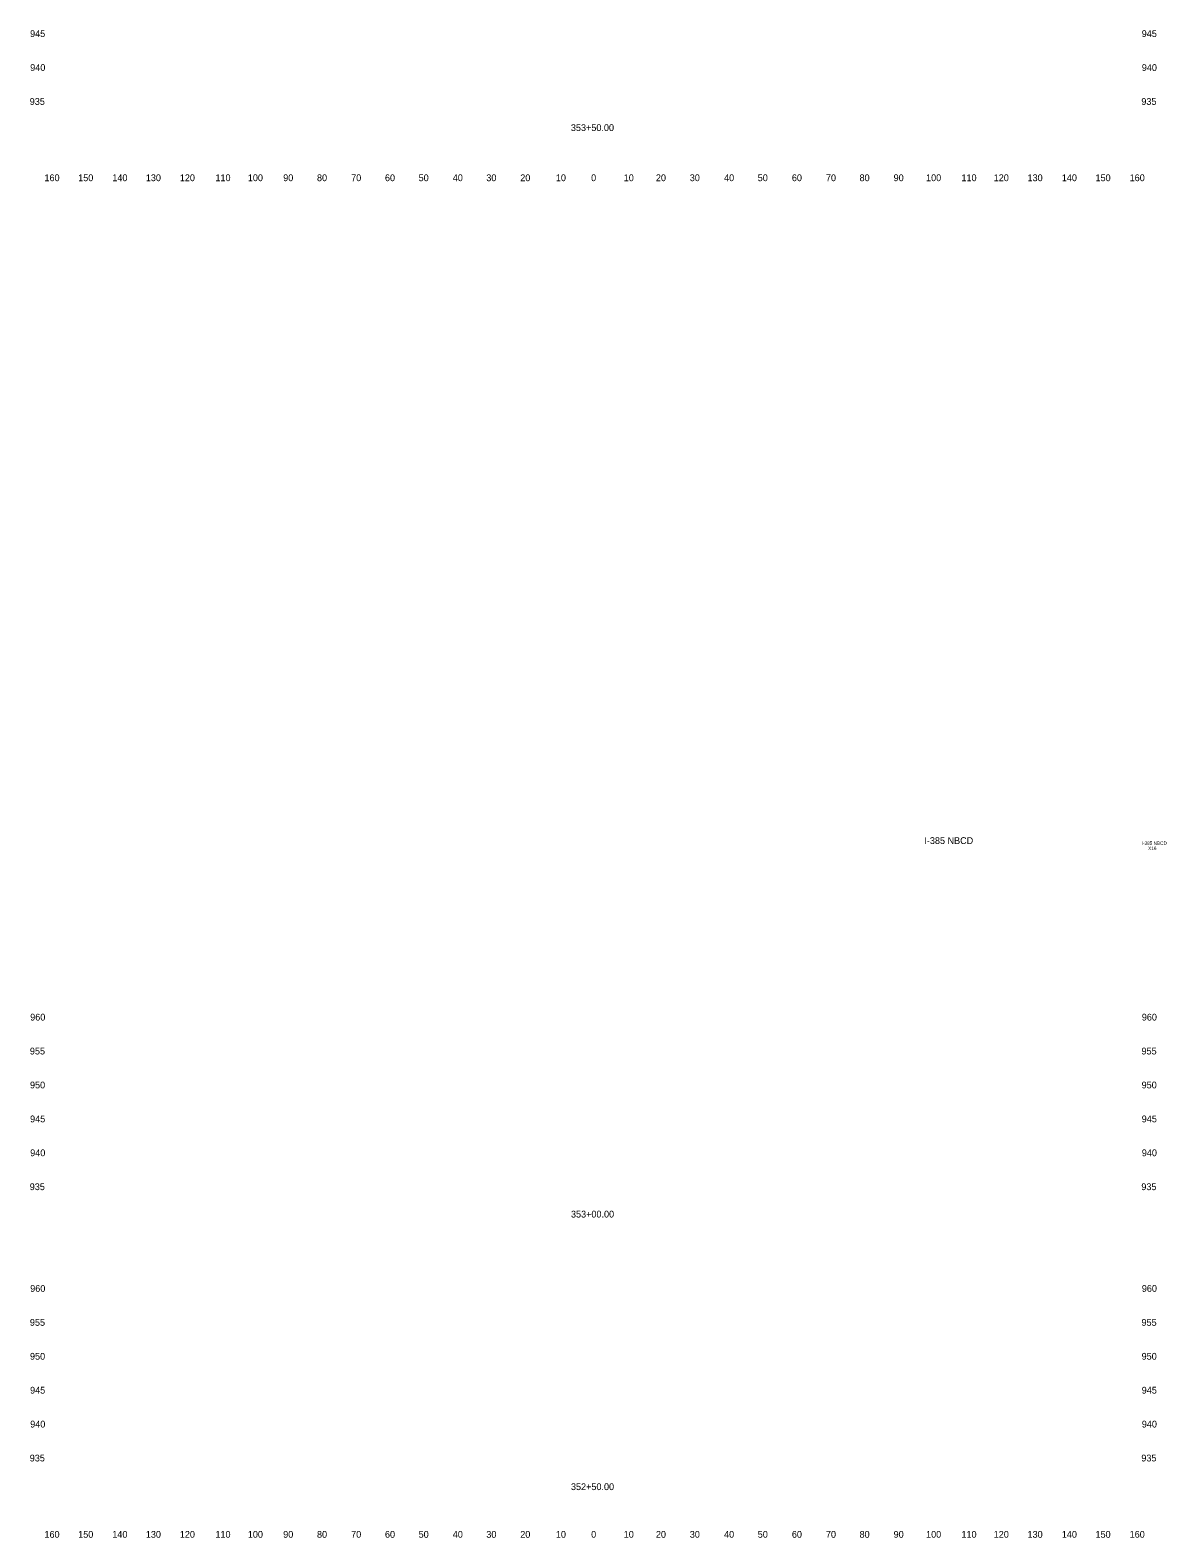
# Model space of a CAD drawing. Extents: x 4994 to 7391, y 4997 to 8804.
# Drawn here: x 5508.9 to 5843.8, y 6997.5 to 7442 of the extents above; entities that cross this region are included whole.
import ezdxf

# ---------------------------------------------------------------- set-up
doc = ezdxf.new("R2010")
doc.units = 0
for name, color, linetype in [('RD_SHT_ID', 7, 'Continuous'), ('RD_XS_TX_Offset', 7, 'Continuous'), ('RD_XS_TX_Station', 7, 'Continuous')]:
    doc.layers.add(name, color=color, linetype=linetype)

msp = doc.modelspace()

# ---------------------------------------------------------------- texts
at = {"layer": 'RD_SHT_ID'}
for s, height, p in [('I-385 NBCD', 2, (5772.56, 7202.06)), ('I-385 NBCD', 1, (5836.63, 7201.8)), ('X16', 1, (5838.55, 7200.3))]:
    msp.add_text(s, height=height, dxfattribs=at).set_placement(p)
at = {"layer": 'RD_XS_TX_Offset'}
for s, p in [('945', (5508.86, 7440)), ('945', (5836.66, 7440)), ('940', (5508.89, 7430)), ('940', (5836.69, 7430)), ('935', (5508.75, 7420)), ('935', (5836.55, 7420)), ('160', (5513.1, 7397.5)), ('150', (5523.04, 7397.5)), ('140', (5533.1, 7397.5)), ('130', (5542.99, 7397.5)), ('120', (5553.01, 7397.5)), ('110', (5563.51, 7397.5)), ('100', (5573.07, 7397.5)), ('90', (5583.5, 7397.5)), ('80', (5593.46, 7397.5)), ('70', (5603.54, 7397.5)), ('60', (5613.5, 7397.5)), ('50', (5623.43, 7397.5)), ('40', (5633.5, 7397.5)), ('30', (5643.39, 7397.5)), ('20', (5653.4, 7397.5)), ('10', (5663.91, 7397.5)), ('0', (5674.3, 7397.5)), ('0', (5674.3, 7397.5)), ('10', (5683.91, 7397.5)), ('20', (5693.4, 7397.5)), ('30', (5703.39, 7397.5)), ('40', (5713.5, 7397.5)), ('50', (5723.43, 7397.5)), ('60', (5733.5, 7397.5)), ('70', (5743.54, 7397.5)), ('80', (5753.46, 7397.5)), ('90', (5763.5, 7397.5)), ('100', (5773.07, 7397.5)), ('110', (5783.51, 7397.5)), ('120', (5793.01, 7397.5)), ('130', (5802.99, 7397.5)), ('140', (5813.1, 7397.5)), ('150', (5823.04, 7397.5)), ('160', (5833.1, 7397.5)), ('960', (5508.89, 7150)), ('960', (5836.69, 7150)), ('955', (5508.8, 7140)), ('955', (5836.6, 7140)), ('950', (5508.83, 7130)), ('950', (5836.63, 7130)), ('945', (5508.86, 7120)), ('945', (5836.66, 7120)), ('940', (5508.89, 7110)), ('940', (5836.69, 7110)), ('935', (5508.75, 7100)), ('935', (5836.55, 7100)), ('960', (5508.89, 7070)), ('960', (5836.69, 7070)), ('955', (5508.8, 7060)), ('955', (5836.6, 7060)), ('950', (5508.83, 7050)), ('950', (5836.63, 7050)), ('945', (5508.86, 7040)), ('945', (5836.66, 7040)), ('940', (5508.89, 7030)), ('940', (5836.69, 7030)), ('935', (5508.75, 7020)), ('935', (5836.55, 7020)), ('160', (5513.1, 6997.5)), ('150', (5523.04, 6997.5)), ('140', (5533.1, 6997.5)), ('130', (5542.99, 6997.5)), ('120', (5553.01, 6997.5)), ('110', (5563.51, 6997.5)), ('100', (5573.07, 6997.5)), ('90', (5583.5, 6997.5)), ('80', (5593.46, 6997.5)), ('70', (5603.54, 6997.5)), ('60', (5613.5, 6997.5)), ('50', (5623.43, 6997.5)), ('40', (5633.5, 6997.5)), ('30', (5643.39, 6997.5)), ('20', (5653.4, 6997.5)), ('10', (5663.91, 6997.5)), ('0', (5674.3, 6997.5)), ('0', (5674.3, 6997.5)), ('10', (5683.91, 6997.5)), ('20', (5693.4, 6997.5)), ('30', (5703.39, 6997.5)), ('40', (5713.5, 6997.5)), ('50', (5723.43, 6997.5)), ('60', (5733.5, 6997.5)), ('70', (5743.54, 6997.5)), ('80', (5753.46, 6997.5)), ('90', (5763.5, 6997.5)), ('100', (5773.07, 6997.5)), ('110', (5783.51, 6997.5)), ('120', (5793.01, 6997.5)), ('130', (5802.99, 6997.5)), ('140', (5813.1, 6997.5)), ('150', (5823.04, 6997.5)), ('160', (5833.1, 6997.5))]:
    msp.add_text(s, height=2, dxfattribs=at).set_placement(p)
at = {"layer": 'RD_XS_TX_Station'}
for s, p in [('353+50.00', (5668.33, 7412.28)), ('353+00.00', (5668.36, 7091.92)), ('352+50.00', (5668.35, 7011.55))]:
    msp.add_text(s, height=2, dxfattribs=at).set_placement(p)

doc.saveas('drawing.dxf')
